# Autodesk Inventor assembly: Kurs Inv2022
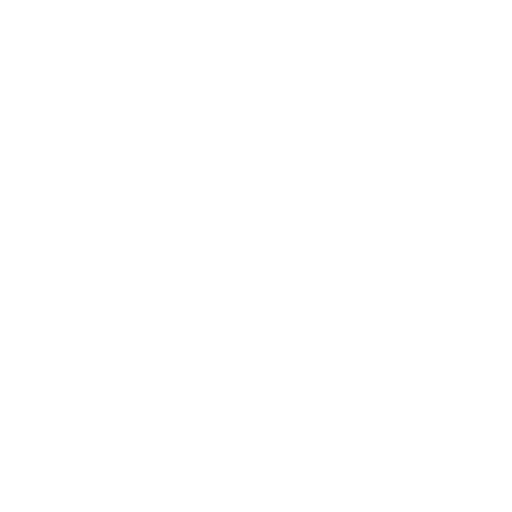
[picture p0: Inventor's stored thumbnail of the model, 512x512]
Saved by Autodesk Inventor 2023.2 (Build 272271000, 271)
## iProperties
Created: 2010-03
Part Number: Kurs Inv2022
Document SubType Name: Assembly
Designer: Johan Wedeen
Manufacturer: Standard
Standards Organization: Custom
Author: Johan Wedeen
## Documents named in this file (1)
- C:\InventorKurs\2023\Kurs Inv2023.iam
